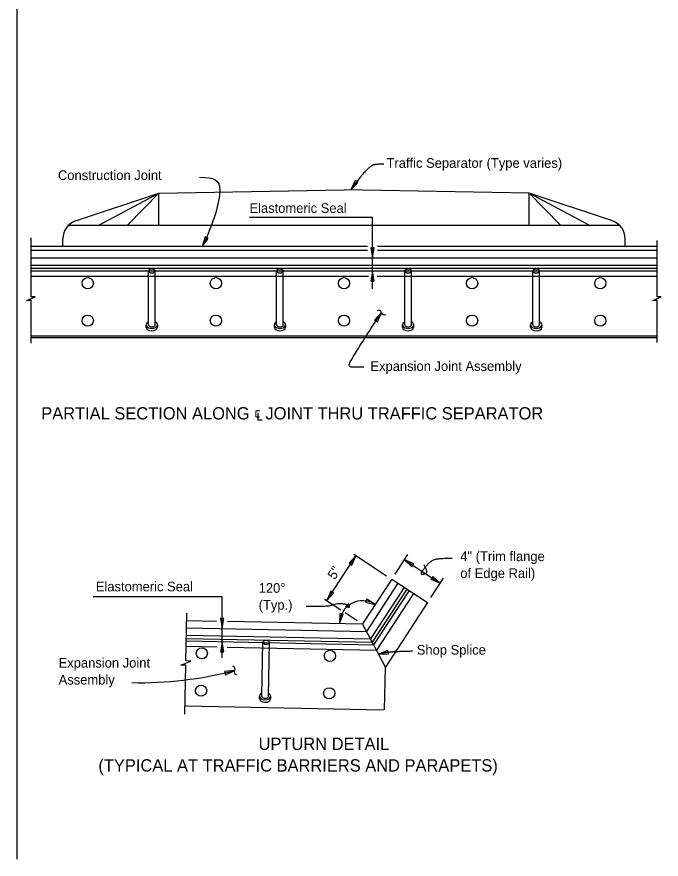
# Model space of a CAD drawing. Extents: x 0 to 26, y -2.5 to 15.3.
# Drawn here: x 10.24 to 15.27, y 0.76 to 7.33 of the extents above; entities that cross this region are included whole.
import ezdxf

# ---------------------------------------------------------------- set-up
doc = ezdxf.new("R2010")
doc.units = 0
for name, color, linetype in [('Dimension', 7, 'Continuous'), ('Miscellaneous', 7, 'Continuous'), ('SteelGirder', 7, 'Continuous'), ('SteelGirder_h', 7, 'Continuous'), ('SupstrConc', 7, 'Continuous'), ('TextStructures', 7, 'Continuous')]:
    doc.layers.add(name, color=color, linetype=linetype)

msp = doc.modelspace()

# ---------------------------------------------------------------- linework, layer by layer
at = {"layer": 'Dimension'}
for p, q in [((10.2417, 10.5), (10.2417, 0.761)), ((12.6601, 2.7793), (12.888, 3.1282)), ((12.8706, 3.1396), (13.1259, 2.9729)), ((13.1944, 2.9854), (13.2934, 3.137)), ((13.2668, 3.0963), (13.5459, 2.9141)), ((13.4735, 2.8031), (13.5725, 2.9547)), ((11.8448, 2.8088), (10.8375, 2.8088)), ((11.8448, 2.5606), (11.8448, 2.8088)), ((12.6427, 2.7907), (12.7704, 2.7073)), ((12.8035, 2.6857), (12.898, 2.624)), ((11.8448, 2.4577), (11.8448, 2.5606)), ((11.8448, 2.3318), (11.8448, 2.4577))]:
    msp.add_line(p, q, dxfattribs=at)
for points in [[(12.8484, 5.9836), (12.904, 6.04), (12.8823, 6.0552)], [(11.6891, 5.5403), (11.7351, 5.6047), (11.7113, 5.6163)], [(13.018, 5.4515), (13.0312, 5.5296), (13.0047, 5.5296)], [(13.018, 5.3485), (13.0047, 5.2704), (13.0312, 5.2704)], [(13.0874, 5.0258), (13.0335, 4.9677), (13.0557, 4.9533)], [(12.888, 3.1281), (12.8342, 3.0699), (12.8563, 3.0555)], [(13.2668, 3.0962), (13.325, 3.0424), (13.3394, 3.0646)], [(13.5459, 2.9139), (13.4877, 2.9677), (13.4733, 2.9455)], [(12.6601, 2.7792), (12.7139, 2.8374), (12.6917, 2.8519)], [(13.0395, 2.7481), (12.9725, 2.7903), (12.9623, 2.7659)], [(11.8448, 2.5605), (11.8581, 2.6386), (11.8316, 2.6386)], [(12.7589, 2.5999), (12.7883, 2.6734), (12.7624, 2.679)], [(11.8448, 2.4576), (11.8316, 2.3795), (11.8581, 2.3795)], [(13.0638, 2.3611), (13.1429, 2.3633), (13.1378, 2.3893)], [(11.9419, 2.2326), (11.863, 2.2257), (11.8697, 2.2001)]]:
    msp.add_lwpolyline(points, close=True, dxfattribs=at)
for points in [[(13.0179, 5.4514), (13.0179, 5.7682), (12.0576, 5.7682)], [(10.3536, 4.7859), (10.3536, 5.121), (10.3206, 5.121), (10.3845, 5.1494), (10.3536, 5.1494), (10.3536, 5.6078)], [(15.2396, 4.7914), (15.2396, 5.121), (15.2065, 5.121), (15.2705, 5.1494), (15.2396, 5.1494), (15.2396, 5.589)], [(13.0179, 5.3486), (13.0179, 5.4514)], [(13.0179, 5.2105), (13.0179, 5.3485)], [(11.5533, 1.891), (11.561, 2.2737), (11.5223, 2.2744), (11.5614, 2.2905), (11.6004, 2.3066), (11.5617, 2.3074), (11.5692, 2.6804)]]:
    msp.add_lwpolyline(points, dxfattribs=at)
for centre, radius, start, end in [((13.0652, 5.0217), 0.0224, 10.95797, 122.68519), ((13.1091, 5.0302), 0.0224, 190.95797, 302.68519), ((12.9403, 2.5964), 0.1814, 56.85433, 178.85433), ((11.9227, 2.2445), 0.0224, 328.74218, 80.4694), ((11.1995, 5.0904), 2.9527, 268.80522, 284.56288), ((11.9609, 2.2213), 0.0224, 148.74218, 260.4694)]:
    msp.add_arc(centre, radius, start, end, dxfattribs=at)
for points, degree in [([(13.1048, 6.1837), (13.0336, 6.1837), (12.9934, 6.1622), (12.9048, 6.0642), (12.8484, 5.9836)], 2), ([(11.6683, 6.0814), (11.7838, 6.0814), (11.8675, 6.05), (11.7804, 5.728), (11.6891, 5.5403)], 3), ([(12.9505, 4.5987), (12.9088, 4.5987), (12.835, 4.5987), (12.835, 4.6404), (13.0874, 5.0258)], 2), ([(13.639, 3.1071), (13.5494, 3.1071), (13.4747, 3.0921), (13.4179, 3.0264), (13.3881, 2.9845), (13.4239, 2.9845), (13.4508, 3.0025), (13.4209, 3.0563)], 2), ([(12.4993, 2.7358), (12.6592, 2.7306), (12.7294, 2.7545), (12.7839, 2.7567), (12.8332, 2.744), (12.8377, 2.7261), (12.828, 2.7246), (12.8033, 2.7313), (12.8317, 2.7545)], 2), ([(13.3309, 2.3829), (13.2382, 2.3809), (13.1368, 2.3757), (13.0638, 2.3611)], 2)]:
    msp.add_open_spline(points, degree=degree, dxfattribs=at)
at = {"layer": 'Miscellaneous'}
for points in [[(15.2396, 5.4514), (10.3537, 5.4514)], [(15.2396, 5.3689), (10.3537, 5.3689)], [(15.2396, 5.3485), (10.3537, 5.3486)], [(13.2165, 2.9137), (12.9712, 2.538)], [(13.2856, 2.8686), (13.0152, 2.4546)], [(13.3026, 2.8575), (13.0261, 2.434)], [(11.5669, 2.5661), (12.9712, 2.538)], [(11.5648, 2.4633), (13.0261, 2.434)], [(11.5652, 2.4836), (13.0152, 2.4546)]]:
    msp.add_lwpolyline(points, dxfattribs=at)
at = {"layer": 'SteelGirder'}
for p, q in [((13.1682, 2.9452), (13.4473, 2.763)), ((13.1184, 2.2594), (12.9403, 2.5964)), ((13.1117, 1.9261), (13.1184, 2.2594))]:
    msp.add_line(p, q, dxfattribs=at)
for points in [[(12.9776, 5.5091), (10.3537, 5.5091)], [(15.2396, 5.5091), (13.0559, 5.5091)], [(15.2396, 4.8424), (10.3537, 4.8424)], [(13.1682, 2.9452), (12.9403, 2.5964)], [(13.4473, 2.763), (13.1184, 2.2594)], [(11.568, 2.6238), (11.8006, 2.6191)], [(11.8869, 2.6174), (12.9403, 2.5964)], [(11.5547, 1.9572), (13.1039, 1.9262)]]:
    msp.add_lwpolyline(points, dxfattribs=at)
at = {"layer": 'SteelGirder_h'}
for p, q in [((11.2691, 4.9307), (11.2691, 5.35)), ((11.3212, 4.9307), (11.3212, 5.35)), ((12.2691, 4.9307), (12.2691, 5.35)), ((12.3212, 4.9307), (12.3212, 5.35)), ((13.2691, 4.9307), (13.2691, 5.35)), ((13.3212, 4.9307), (13.3212, 5.35)), ((14.2691, 4.9307), (14.2691, 5.35)), ((14.3212, 4.9307), (14.3212, 5.35)), ((11.2516, 4.911), (11.2516, 4.9307)), ((11.3388, 4.9307), (11.3388, 4.911)), ((12.2516, 4.911), (12.2516, 4.9307)), ((12.3388, 4.9307), (12.3388, 4.911)), ((13.2516, 4.911), (13.2516, 4.9307)), ((13.3388, 4.9307), (13.3388, 4.911)), ((14.2516, 4.911), (14.2516, 4.9307)), ((14.3388, 4.9307), (14.3388, 4.911)), ((12.1529, 2.0336), (12.1613, 2.4528)), ((12.205, 2.0326), (12.2134, 2.4517)), ((12.1349, 2.0142), (12.1353, 2.034)), ((12.2225, 2.0322), (12.2221, 2.0125))]:
    msp.add_line(p, q, dxfattribs=at)
for points in [[(15.2396, 5.3931), (10.3537, 5.3931)], [(12.9872, 5.3068), (10.3537, 5.3068)], [(15.2396, 5.3068), (13.0531, 5.3068)], [(13.2653, 2.8818), (13.0023, 2.4791)], [(13.3375, 2.8347), (13.0484, 2.3919)], [(11.5657, 2.5078), (13.0023, 2.4791)], [(11.564, 2.4216), (11.8047, 2.4168)], [(11.8828, 2.4152), (13.0484, 2.3919)]]:
    msp.add_lwpolyline(points, dxfattribs=at)
for centre in [(10.7952, 5.2547), (11.7952, 5.2547), (12.7952, 5.2547), (13.7952, 5.2547), (14.7952, 5.2547), (10.7952, 4.963), (11.7952, 4.963), (12.7952, 4.963), (13.7952, 4.963), (14.7952, 4.963), (11.6855, 2.367), (12.6853, 2.347), (11.6797, 2.0754), (12.6795, 2.0554)]:
    msp.add_circle(centre, 0.0436, dxfattribs=at)
for centre, major_axis in [((11.2952, 5.35), (0.0261, 0)), ((12.2952, 5.35), (0.0261, 0)), ((13.2952, 5.35), (0.0261, 0)), ((14.2952, 5.35), (0.0261, 0)), ((12.1873, 2.4523), (0.026, -0.0005))]:
    msp.add_ellipse(centre, major_axis=major_axis, ratio=0.654774, dxfattribs=at)
for centre, major_axis, ratio, start_param, end_param in [((11.2952, 4.9307), (0.0436, 0), 0.654766, 2.211147, 7.21363), ((11.2952, 4.9307), (0.0261, 0), 0.654774, 3.1416, 6.283178), ((12.2952, 4.9307), (0.0436, 0), 0.654766, 2.211147, 7.21363), ((12.2952, 4.9307), (0.0261, 0), 0.654774, 3.1416, 6.283178), ((13.2952, 4.9307), (0.0436, 0), 0.654766, 2.211147, 7.21363), ((13.2952, 4.9307), (0.0261, 0), 0.654774, 3.1416, 6.283178), ((14.2952, 4.9307), (0.0436, 0), 0.654766, 2.211147, 7.21363), ((14.2952, 4.9307), (0.0261, 0), 0.654774, 3.1416, 6.283178), ((11.2952, 4.911), (0.0436, 0), 0.654766, 3.141593, 6.283185), ((12.2952, 4.911), (0.0436, 0), 0.654766, 3.141593, 6.283185), ((13.2952, 4.911), (0.0436, 0), 0.654766, 3.141593, 6.283185), ((14.2952, 4.911), (0.0436, 0), 0.654766, 3.141593, 6.283185), ((12.1789, 2.0331), (0.0436, -0.0009), 0.654766, 2.211147, 7.21363), ((12.1785, 2.0134), (0.0436, -0.0009), 0.654766, 3.141593, 6.283185), ((12.1789, 2.0331), (0.026, -0.0005), 0.654774, 3.1416, 6.283178)]:
    msp.add_ellipse(centre, major_axis=major_axis, ratio=ratio, start_param=start_param, end_param=end_param, dxfattribs=at)
at = {"layer": 'SupstrConc'}
for p, q in [((11.3505, 5.957), (12.7952, 5.9838)), ((14.2398, 5.957), (12.7952, 5.9838)), ((10.7002, 5.7403), (11.3505, 5.957)), ((10.8857, 5.7112), (11.3505, 5.957)), ((11.1073, 5.7099), (11.3505, 5.957)), ((11.3505, 5.7071), (11.3505, 5.957)), ((14.8901, 5.7403), (14.2398, 5.957)), ((14.2398, 5.7071), (14.2398, 5.957)), ((14.7046, 5.7112), (14.2398, 5.957)), ((14.483, 5.7099), (14.2398, 5.957)), ((10.6454, 5.7071), (14.9449, 5.7071)), ((10.6005, 5.5403), (10.6005, 5.6019)), ((14.9898, 5.5403), (14.9898, 5.6019)), ((10.3536, 4.832), (15.2396, 4.832))]:
    msp.add_line(p, q, dxfattribs=at)
for points in [[(12.9776, 5.5403), (10.3537, 5.5403)], [(15.2396, 5.5403), (13.0559, 5.5403)]]:
    msp.add_lwpolyline(points, dxfattribs=at)
for centre, start, end in [((10.7463, 5.6019), 108.43495, 180), ((14.844, 5.6019), 0, 71.56505)]:
    msp.add_arc(centre, 0.1458, start, end, dxfattribs=at)

# ---------------------------------------------------------------- texts
at = {"layer": 'TextStructures'}
for s, height, p in [('Traffic Separator (Type varies)', 0.0756, (13.1269, 6.1551)), ('Construction Joint', 0.0756, (10.5626, 6.0599)), ('Elastomeric Seal', 0.0756, (12.0571, 5.8031)), ('Expansion Joint Assembly', 0.0756, (13.0012, 4.5702)), ('PARTIAL SECTION ALONG ℄ JOINT THRU TRAFFIC SEPARATOR', 0.096, (10.4321, 4.1915)), ('4" (Trim flange', 0.0756, (13.7027, 3.0865)), ('of Edge Rail)', 0.0756, (13.7027, 2.9545)), ('Elastomeric Seal', 0.0756, (10.8579, 2.8504)), ('120° ', 0.0756, (12.129, 2.8391)), ('(Typ.)', 0.0756, (12.129, 2.7071)), ('Shop Splice', 0.0756, (13.3628, 2.3566)), ('Expansion Joint', 0.0756, (10.5677, 2.2554)), ('Assembly', 0.0756, (10.5677, 2.1234)), ('UPTURN DETAIL', 0.096, (12.1284, 1.6126)), ('(TYPICAL AT TRAFFIC BARRIERS AND PARAPETS)', 0.096, (10.8782, 1.4446))]:
    msp.add_text(s, height=height, dxfattribs=at).set_placement(p)
msp.add_text('5"', height=0.0756, rotation=56.85433, dxfattribs=at).set_placement((12.7238, 2.9365))

doc.saveas('drawing.dxf')
